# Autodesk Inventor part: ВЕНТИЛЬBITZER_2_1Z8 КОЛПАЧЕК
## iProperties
Created: 2011-02
Part Number: ВЕНТИЛЬBITZER_2_1Z8 КОЛПАЧЕК
Document SubType Name: Modeling
Designer: Чернышев Юрий
Mass: 71.9651 g
Surface Area: 104.154 cm^2
Volume: 71.9651 cm^3
Density: 1 g/cm^3
Author: Чернышев Юрий
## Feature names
1. RevolutionAngle1
